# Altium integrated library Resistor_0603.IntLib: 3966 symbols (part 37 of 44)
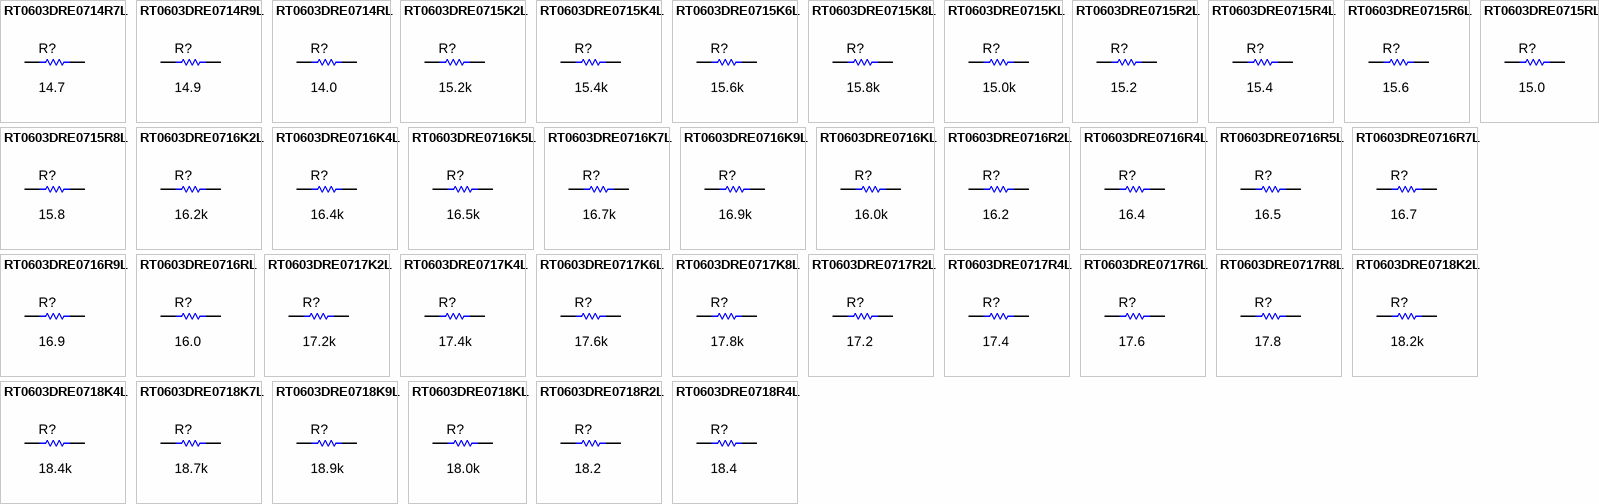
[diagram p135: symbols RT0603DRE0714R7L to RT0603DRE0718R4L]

## RT0603DRE0715R2L
designator R?  ValueDisplayed: 15.2  (hidden comment: RT0603DRE0715R2L)
RES, 15.2, 0.5%, 0.1 W, 0603; Manufacturer: Yageo America; CompType: Resistor; Value: 15.2; Value_Code: 15R2; Tolerance_%: 0.5; Power_W: 0.1; Value2: 0.1W; VDC_V: 75; TempCo: 50 ppm/C; SizeArea_mm2: 1.28; SizeX_mm: 1.6; SizeY_mm: 0.8; SizeZ_mm: 1; EIA_Code: E192; U/M: EA; AEC Category: Q200
signal-integrity model Resistor
simulation model Resistor
footprint 0603
footprint 0603M
footprint 0603L
footprint 0603_HV
footprint 0603S
pins: 1, 2

## RT0603DRE0715R4L
designator R?  ValueDisplayed: 15.4  (hidden comment: RT0603DRE0715R4L)
RES, 15.4, 0.5%, 0.1 W, 0603; Manufacturer: Yageo America; CompType: Resistor; Value: 15.4; Value_Code: 15R4; Tolerance_%: 0.5; Power_W: 0.1; Value2: 0.1W; VDC_V: 75; TempCo: 50 ppm/C; SizeArea_mm2: 1.28; SizeX_mm: 1.6; SizeY_mm: 0.8; SizeZ_mm: 1; EIA_Code: E192; U/M: EA; AEC Category: Q200
signal-integrity model Resistor
simulation model Resistor
footprint 0603
footprint 0603M
footprint 0603L
footprint 0603_HV
footprint 0603S
pins: 1, 2

## RT0603DRE0715R6L
designator R?  ValueDisplayed: 15.6  (hidden comment: RT0603DRE0715R6L)
RES, 15.6, 0.5%, 0.1 W, 0603; Manufacturer: Yageo America; CompType: Resistor; Value: 15.6; Value_Code: 15R6; Tolerance_%: 0.5; Power_W: 0.1; Value2: 0.1W; VDC_V: 75; TempCo: 50 ppm/C; SizeArea_mm2: 1.28; SizeX_mm: 1.6; SizeY_mm: 0.8; SizeZ_mm: 1; EIA_Code: E192; U/M: EA; AEC Category: Q200
signal-integrity model Resistor
simulation model Resistor
footprint 0603
footprint 0603M
footprint 0603L
footprint 0603_HV
footprint 0603S
pins: 1, 2

## RT0603DRE0715R8L
designator R?  ValueDisplayed: 15.8  (hidden comment: RT0603DRE0715R8L)
RES, 15.8, 0.5%, 0.1 W, 0603; Manufacturer: Yageo America; CompType: Resistor; Value: 15.8; Value_Code: 15R8; Tolerance_%: 0.5; Power_W: 0.1; Value2: 0.1W; VDC_V: 75; TempCo: 50 ppm/C; SizeArea_mm2: 1.28; SizeX_mm: 1.6; SizeY_mm: 0.8; SizeZ_mm: 1; EIA_Code: E192; U/M: EA; AEC Category: Q200
signal-integrity model Resistor
simulation model Resistor
footprint 0603
footprint 0603M
footprint 0603L
footprint 0603_HV
footprint 0603S
pins: 1, 2

## RT0603DRE0715RL
designator R?  ValueDisplayed: 15.0  (hidden comment: RT0603DRE0715RL)
RES, 15.0, 0.5%, 0.1 W, 0603; Manufacturer: Yageo America; CompType: Resistor; Value: 15.0; Res_ohm: 15; Value_Code: 15R0; Tolerance_%: 0.5; Power_W: 0.1; Value2: 0.1W; VDC_V: 75; TempCo: 50 ppm/C; SizeArea_mm2: 1.28; SizeX_mm: 1.6; SizeY_mm: 0.8; SizeZ_mm: 1; EIA_Code: E192; U/M: EA; AEC Category: Q200
signal-integrity model Resistor
simulation model Resistor
footprint 0603
footprint 0603M
footprint 0603L
footprint 0603_HV
footprint 0603S
pins: 1, 2

## RT0603DRE0716K2L
designator R?  ValueDisplayed: 16.2k  (hidden comment: RT0603DRE0716K2L)
RES, 16.2 k, 0.5%, 0.1 W, 0603; Manufacturer: Yageo America; CompType: Resistor; Value: 16.2k; Res_ohm: 16200; Value_Code: 16k2; Tolerance_%: 0.5; Power_W: 0.1; Value2: 0.1W; VDC_V: 75; TempCo: 50 ppm/C; SizeArea_mm2: 1.28; SizeX_mm: 1.6; SizeY_mm: 0.8; SizeZ_mm: 1; EIA_Code: E192; U/M: EA; AEC Category: Q200
signal-integrity model Resistor
simulation model Resistor
footprint 0603
footprint 0603M
footprint 0603L
footprint 0603_HV
footprint 0603S
pins: 1, 2

## RT0603DRE0716K4L
designator R?  ValueDisplayed: 16.4k  (hidden comment: RT0603DRE0716K4L)
RES, 16.4 k, 0.5%, 0.1 W, 0603; Manufacturer: Yageo America; CompType: Resistor; Value: 16.4k; Res_ohm: 16400; Value_Code: 16k4; Tolerance_%: 0.5; Power_W: 0.1; Value2: 0.1W; VDC_V: 75; TempCo: 50 ppm/C; SizeArea_mm2: 1.28; SizeX_mm: 1.6; SizeY_mm: 0.8; SizeZ_mm: 1; EIA_Code: E192; U/M: EA; AEC Category: Q200
signal-integrity model Resistor
simulation model Resistor
footprint 0603
footprint 0603M
footprint 0603L
footprint 0603_HV
footprint 0603S
pins: 1, 2

## RT0603DRE0716K5L
designator R?  ValueDisplayed: 16.5k  (hidden comment: RT0603DRE0716K5L)
RES, 16.5 k, 0.5%, 0.1 W, 0603; Manufacturer: Yageo America; CompType: Resistor; Value: 16.5k; Res_ohm: 16500; Value_Code: 16k5; Tolerance_%: 0.5; Power_W: 0.1; Value2: 0.1W; VDC_V: 75; TempCo: 50 ppm/C; SizeArea_mm2: 1.28; SizeX_mm: 1.6; SizeY_mm: 0.8; SizeZ_mm: 1; EIA_Code: E192; U/M: EA; AEC Category: Q200
signal-integrity model Resistor
simulation model Resistor
footprint 0603
footprint 0603M
footprint 0603L
footprint 0603_HV
footprint 0603S
pins: 1, 2

## RT0603DRE0716K7L
designator R?  ValueDisplayed: 16.7k  (hidden comment: RT0603DRE0716K7L)
RES, 16.7 k, 0.5%, 0.1 W, 0603; Manufacturer: Yageo America; CompType: Resistor; Value: 16.7k; Res_ohm: 16700; Value_Code: 16k7; Tolerance_%: 0.5; Power_W: 0.1; Value2: 0.1W; VDC_V: 75; TempCo: 50 ppm/C; SizeArea_mm2: 1.28; SizeX_mm: 1.6; SizeY_mm: 0.8; SizeZ_mm: 1; EIA_Code: E192; U/M: EA; AEC Category: Q200
signal-integrity model Resistor
simulation model Resistor
footprint 0603
footprint 0603M
footprint 0603L
footprint 0603_HV
footprint 0603S
pins: 1, 2

## RT0603DRE0716K9L
designator R?  ValueDisplayed: 16.9k  (hidden comment: RT0603DRE0716K9L)
RES, 16.9 k, 0.5%, 0.1 W, 0603; Manufacturer: Yageo America; CompType: Resistor; Value: 16.9k; Res_ohm: 16900; Value_Code: 16k9; Tolerance_%: 0.5; Power_W: 0.1; Value2: 0.1W; VDC_V: 75; TempCo: 50 ppm/C; SizeArea_mm2: 1.28; SizeX_mm: 1.6; SizeY_mm: 0.8; SizeZ_mm: 1; EIA_Code: E192; U/M: EA; AEC Category: Q200
signal-integrity model Resistor
simulation model Resistor
footprint 0603
footprint 0603M
footprint 0603L
footprint 0603_HV
footprint 0603S
pins: 1, 2

## RT0603DRE0716KL
designator R?  ValueDisplayed: 16.0k  (hidden comment: RT0603DRE0716KL)
RES, 16.0 k, 0.5%, 0.1 W, 0603; Manufacturer: Yageo America; CompType: Resistor; Value: 16.0k; Res_ohm: 16000; Value_Code: 16k0; Tolerance_%: 0.5; Power_W: 0.1; Value2: 0.1W; VDC_V: 75; TempCo: 50 ppm/C; SizeArea_mm2: 1.28; SizeX_mm: 1.6; SizeY_mm: 0.8; SizeZ_mm: 1; EIA_Code: E192; U/M: EA; AEC Category: Q200
signal-integrity model Resistor
simulation model Resistor
footprint 0603
footprint 0603M
footprint 0603L
footprint 0603_HV
footprint 0603S
pins: 1, 2

## RT0603DRE0716R2L
designator R?  ValueDisplayed: 16.2  (hidden comment: RT0603DRE0716R2L)
RES, 16.2, 0.5%, 0.1 W, 0603; Manufacturer: Yageo America; CompType: Resistor; Value: 16.2; Value_Code: 16R2; Tolerance_%: 0.5; Power_W: 0.1; Value2: 0.1W; VDC_V: 75; TempCo: 50 ppm/C; SizeArea_mm2: 1.28; SizeX_mm: 1.6; SizeY_mm: 0.8; SizeZ_mm: 1; EIA_Code: E192; U/M: EA; AEC Category: Q200
signal-integrity model Resistor
simulation model Resistor
footprint 0603
footprint 0603M
footprint 0603L
footprint 0603_HV
footprint 0603S
pins: 1, 2

## RT0603DRE0716R4L
designator R?  ValueDisplayed: 16.4  (hidden comment: RT0603DRE0716R4L)
RES, 16.4, 0.5%, 0.1 W, 0603; Manufacturer: Yageo America; CompType: Resistor; Value: 16.4; Value_Code: 16R4; Tolerance_%: 0.5; Power_W: 0.1; Value2: 0.1W; VDC_V: 75; TempCo: 50 ppm/C; SizeArea_mm2: 1.28; SizeX_mm: 1.6; SizeY_mm: 0.8; SizeZ_mm: 1; EIA_Code: E192; U/M: EA; AEC Category: Q200
signal-integrity model Resistor
simulation model Resistor
footprint 0603
footprint 0603M
footprint 0603L
footprint 0603_HV
footprint 0603S
pins: 1, 2

## RT0603DRE0716R5L
designator R?  ValueDisplayed: 16.5  (hidden comment: RT0603DRE0716R5L)
RES, 16.5, 0.5%, 0.1 W, 0603; Manufacturer: Yageo America; CompType: Resistor; Value: 16.5; Value_Code: 16R5; Tolerance_%: 0.5; Power_W: 0.1; Value2: 0.1W; VDC_V: 75; TempCo: 50 ppm/C; SizeArea_mm2: 1.28; SizeX_mm: 1.6; SizeY_mm: 0.8; SizeZ_mm: 1; EIA_Code: E192; U/M: EA; AEC Category: Q200
signal-integrity model Resistor
simulation model Resistor
footprint 0603
footprint 0603M
footprint 0603L
footprint 0603_HV
footprint 0603S
pins: 1, 2

## RT0603DRE0716R7L
designator R?  ValueDisplayed: 16.7  (hidden comment: RT0603DRE0716R7L)
RES, 16.7, 0.5%, 0.1 W, 0603; Manufacturer: Yageo America; CompType: Resistor; Value: 16.7; Value_Code: 16R7; Tolerance_%: 0.5; Power_W: 0.1; Value2: 0.1W; VDC_V: 75; TempCo: 50 ppm/C; SizeArea_mm2: 1.28; SizeX_mm: 1.6; SizeY_mm: 0.8; SizeZ_mm: 1; EIA_Code: E192; U/M: EA; AEC Category: Q200
signal-integrity model Resistor
simulation model Resistor
footprint 0603
footprint 0603M
footprint 0603L
footprint 0603_HV
footprint 0603S
pins: 1, 2

## RT0603DRE0716R9L
designator R?  ValueDisplayed: 16.9  (hidden comment: RT0603DRE0716R9L)
RES, 16.9, 0.5%, 0.1 W, 0603; Manufacturer: Yageo America; CompType: Resistor; Value: 16.9; Value_Code: 16R9; Tolerance_%: 0.5; Power_W: 0.1; Value2: 0.1W; VDC_V: 75; TempCo: 50 ppm/C; SizeArea_mm2: 1.28; SizeX_mm: 1.6; SizeY_mm: 0.8; SizeZ_mm: 1; EIA_Code: E192; U/M: EA; AEC Category: Q200
signal-integrity model Resistor
simulation model Resistor
footprint 0603
footprint 0603M
footprint 0603L
footprint 0603_HV
footprint 0603S
pins: 1, 2

## RT0603DRE0716RL
designator R?  ValueDisplayed: 16.0  (hidden comment: RT0603DRE0716RL)
RES, 16.0, 0.5%, 0.1 W, 0603; Manufacturer: Yageo America; CompType: Resistor; Value: 16.0; Res_ohm: 16; Value_Code: 16R0; Tolerance_%: 0.5; Power_W: 0.1; Value2: 0.1W; VDC_V: 75; TempCo: 50 ppm/C; SizeArea_mm2: 1.28; SizeX_mm: 1.6; SizeY_mm: 0.8; SizeZ_mm: 1; EIA_Code: E192; U/M: EA; AEC Category: Q200
signal-integrity model Resistor
simulation model Resistor
footprint 0603
footprint 0603M
footprint 0603L
footprint 0603_HV
footprint 0603S
pins: 1, 2

## RT0603DRE0717K2L
designator R?  ValueDisplayed: 17.2k  (hidden comment: RT0603DRE0717K2L)
RES, 17.2 k, 0.5%, 0.1 W, 0603; Manufacturer: Yageo America; CompType: Resistor; Value: 17.2k; Res_ohm: 17200; Value_Code: 17k2; Tolerance_%: 0.5; Power_W: 0.1; Value2: 0.1W; VDC_V: 75; TempCo: 50 ppm/C; SizeArea_mm2: 1.28; SizeX_mm: 1.6; SizeY_mm: 0.8; SizeZ_mm: 1; EIA_Code: E192; U/M: EA; AEC Category: Q200
signal-integrity model Resistor
simulation model Resistor
footprint 0603
footprint 0603M
footprint 0603L
footprint 0603_HV
footprint 0603S
pins: 1, 2

## RT0603DRE0717K4L
designator R?  ValueDisplayed: 17.4k  (hidden comment: RT0603DRE0717K4L)
RES, 17.4 k, 0.5%, 0.1 W, 0603; Manufacturer: Yageo America; CompType: Resistor; Value: 17.4k; Res_ohm: 17400; Value_Code: 17k4; Tolerance_%: 0.5; Power_W: 0.1; Value2: 0.1W; VDC_V: 75; TempCo: 50 ppm/C; SizeArea_mm2: 1.28; SizeX_mm: 1.6; SizeY_mm: 0.8; SizeZ_mm: 1; EIA_Code: E192; U/M: EA; AEC Category: Q200
signal-integrity model Resistor
simulation model Resistor
footprint 0603
footprint 0603M
footprint 0603L
footprint 0603_HV
footprint 0603S
pins: 1, 2

## RT0603DRE0717K6L
designator R?  ValueDisplayed: 17.6k  (hidden comment: RT0603DRE0717K6L)
RES, 17.6 k, 0.5%, 0.1 W, 0603; Manufacturer: Yageo America; CompType: Resistor; Value: 17.6k; Res_ohm: 17600; Value_Code: 17k6; Tolerance_%: 0.5; Power_W: 0.1; Value2: 0.1W; VDC_V: 75; TempCo: 50 ppm/C; SizeArea_mm2: 1.28; SizeX_mm: 1.6; SizeY_mm: 0.8; SizeZ_mm: 1; EIA_Code: E192; U/M: EA; AEC Category: Q200
signal-integrity model Resistor
simulation model Resistor
footprint 0603
footprint 0603M
footprint 0603L
footprint 0603_HV
footprint 0603S
pins: 1, 2

## RT0603DRE0717K8L
designator R?  ValueDisplayed: 17.8k  (hidden comment: RT0603DRE0717K8L)
RES, 17.8 k, 0.5%, 0.1 W, 0603; Manufacturer: Yageo America; CompType: Resistor; Value: 17.8k; Res_ohm: 17800; Value_Code: 17k8; Tolerance_%: 0.5; Power_W: 0.1; Value2: 0.1W; VDC_V: 75; TempCo: 50 ppm/C; SizeArea_mm2: 1.28; SizeX_mm: 1.6; SizeY_mm: 0.8; SizeZ_mm: 1; EIA_Code: E192; U/M: EA; AEC Category: Q200
signal-integrity model Resistor
simulation model Resistor
footprint 0603
footprint 0603M
footprint 0603L
footprint 0603_HV
footprint 0603S
pins: 1, 2

## RT0603DRE0717R2L
designator R?  ValueDisplayed: 17.2  (hidden comment: RT0603DRE0717R2L)
RES, 17.2, 0.5%, 0.1 W, 0603; Manufacturer: Yageo America; CompType: Resistor; Value: 17.2; Value_Code: 17R2; Tolerance_%: 0.5; Power_W: 0.1; Value2: 0.1W; VDC_V: 75; TempCo: 50 ppm/C; SizeArea_mm2: 1.28; SizeX_mm: 1.6; SizeY_mm: 0.8; SizeZ_mm: 1; EIA_Code: E192; U/M: EA; AEC Category: Q200
signal-integrity model Resistor
simulation model Resistor
footprint 0603
footprint 0603M
footprint 0603L
footprint 0603_HV
footprint 0603S
pins: 1, 2

## RT0603DRE0717R4L
designator R?  ValueDisplayed: 17.4  (hidden comment: RT0603DRE0717R4L)
RES, 17.4, 0.5%, 0.1 W, 0603; Manufacturer: Yageo America; CompType: Resistor; Value: 17.4; Value_Code: 17R4; Tolerance_%: 0.5; Power_W: 0.1; Value2: 0.1W; VDC_V: 75; TempCo: 50 ppm/C; SizeArea_mm2: 1.28; SizeX_mm: 1.6; SizeY_mm: 0.8; SizeZ_mm: 1; EIA_Code: E192; U/M: EA; AEC Category: Q200
signal-integrity model Resistor
simulation model Resistor
footprint 0603
footprint 0603M
footprint 0603L
footprint 0603_HV
footprint 0603S
pins: 1, 2

## RT0603DRE0717R6L
designator R?  ValueDisplayed: 17.6  (hidden comment: RT0603DRE0717R6L)
RES, 17.6, 0.5%, 0.1 W, 0603; Manufacturer: Yageo America; CompType: Resistor; Value: 17.6; Value_Code: 17R6; Tolerance_%: 0.5; Power_W: 0.1; Value2: 0.1W; VDC_V: 75; TempCo: 50 ppm/C; SizeArea_mm2: 1.28; SizeX_mm: 1.6; SizeY_mm: 0.8; SizeZ_mm: 1; EIA_Code: E192; U/M: EA; AEC Category: Q200
signal-integrity model Resistor
simulation model Resistor
footprint 0603
footprint 0603M
footprint 0603L
footprint 0603_HV
footprint 0603S
pins: 1, 2

## RT0603DRE0717R8L
designator R?  ValueDisplayed: 17.8  (hidden comment: RT0603DRE0717R8L)
RES, 17.8, 0.5%, 0.1 W, 0603; Manufacturer: Yageo America; CompType: Resistor; Value: 17.8; Value_Code: 17R8; Tolerance_%: 0.5; Power_W: 0.1; Value2: 0.1W; VDC_V: 75; TempCo: 50 ppm/C; SizeArea_mm2: 1.28; SizeX_mm: 1.6; SizeY_mm: 0.8; SizeZ_mm: 1; EIA_Code: E192; U/M: EA; AEC Category: Q200
signal-integrity model Resistor
simulation model Resistor
footprint 0603
footprint 0603M
footprint 0603L
footprint 0603_HV
footprint 0603S
pins: 1, 2

## RT0603DRE0718K2L
designator R?  ValueDisplayed: 18.2k  (hidden comment: RT0603DRE0718K2L)
RES, 18.2 k, 0.5%, 0.1 W, 0603; Manufacturer: Yageo America; CompType: Resistor; Value: 18.2k; Res_ohm: 18200; Value_Code: 18k2; Tolerance_%: 0.5; Power_W: 0.1; Value2: 0.1W; VDC_V: 75; TempCo: 50 ppm/C; SizeArea_mm2: 1.28; SizeX_mm: 1.6; SizeY_mm: 0.8; SizeZ_mm: 1; EIA_Code: E192; U/M: EA; AEC Category: Q200
signal-integrity model Resistor
simulation model Resistor
footprint 0603
footprint 0603M
footprint 0603L
footprint 0603_HV
footprint 0603S
pins: 1, 2

## RT0603DRE0718K4L
designator R?  ValueDisplayed: 18.4k  (hidden comment: RT0603DRE0718K4L)
RES, 18.4 k, 0.5%, 0.1 W, 0603; Manufacturer: Yageo America; CompType: Resistor; Value: 18.4k; Res_ohm: 18400; Value_Code: 18k4; Tolerance_%: 0.5; Power_W: 0.1; Value2: 0.1W; VDC_V: 75; TempCo: 50 ppm/C; SizeArea_mm2: 1.28; SizeX_mm: 1.6; SizeY_mm: 0.8; SizeZ_mm: 1; EIA_Code: E192; U/M: EA; AEC Category: Q200
signal-integrity model Resistor
simulation model Resistor
footprint 0603
footprint 0603M
footprint 0603L
footprint 0603_HV
footprint 0603S
pins: 1, 2

## RT0603DRE0718K7L
designator R?  ValueDisplayed: 18.7k  (hidden comment: RT0603DRE0718K7L)
RES, 18.7 k, 0.5%, 0.1 W, 0603; Manufacturer: Yageo America; CompType: Resistor; Value: 18.7k; Res_ohm: 18700; Value_Code: 18k7; Tolerance_%: 0.5; Power_W: 0.1; Value2: 0.1W; VDC_V: 75; TempCo: 50 ppm/C; SizeArea_mm2: 1.28; SizeX_mm: 1.6; SizeY_mm: 0.8; SizeZ_mm: 1; EIA_Code: E192; U/M: EA; AEC Category: Q200
signal-integrity model Resistor
simulation model Resistor
footprint 0603
footprint 0603M
footprint 0603L
footprint 0603_HV
footprint 0603S
pins: 1, 2

## RT0603DRE0718K9L
designator R?  ValueDisplayed: 18.9k  (hidden comment: RT0603DRE0718K9L)
RES, 18.9 k, 0.5%, 0.1 W, 0603; Manufacturer: Yageo America; CompType: Resistor; Value: 18.9k; Res_ohm: 18900; Value_Code: 18k9; Tolerance_%: 0.5; Power_W: 0.1; Value2: 0.1W; VDC_V: 75; TempCo: 50 ppm/C; SizeArea_mm2: 1.28; SizeX_mm: 1.6; SizeY_mm: 0.8; SizeZ_mm: 1; EIA_Code: E192; U/M: EA; AEC Category: Q200
signal-integrity model Resistor
simulation model Resistor
footprint 0603
footprint 0603M
footprint 0603L
footprint 0603_HV
footprint 0603S
pins: 1, 2

## RT0603DRE0718KL
designator R?  ValueDisplayed: 18.0k  (hidden comment: RT0603DRE0718KL)
RES, 18.0 k, 0.5%, 0.1 W, 0603; Manufacturer: Yageo America; CompType: Resistor; Value: 18.0k; Res_ohm: 18000; Value_Code: 18k0; Tolerance_%: 0.5; Power_W: 0.1; Value2: 0.1W; VDC_V: 75; TempCo: 50 ppm/C; SizeArea_mm2: 1.28; SizeX_mm: 1.6; SizeY_mm: 0.8; SizeZ_mm: 1; EIA_Code: E192; U/M: EA; AEC Category: Q200
signal-integrity model Resistor
simulation model Resistor
footprint 0603
footprint 0603M
footprint 0603L
footprint 0603_HV
footprint 0603S
pins: 1, 2

## RT0603DRE0718R2L
designator R?  ValueDisplayed: 18.2  (hidden comment: RT0603DRE0718R2L)
RES, 18.2, 0.5%, 0.1 W, 0603; Manufacturer: Yageo America; CompType: Resistor; Value: 18.2; Value_Code: 18R2; Tolerance_%: 0.5; Power_W: 0.1; Value2: 0.1W; VDC_V: 75; TempCo: 50 ppm/C; SizeArea_mm2: 1.28; SizeX_mm: 1.6; SizeY_mm: 0.8; SizeZ_mm: 1; EIA_Code: E192; U/M: EA; AEC Category: Q200
signal-integrity model Resistor
simulation model Resistor
footprint 0603
footprint 0603M
footprint 0603L
footprint 0603_HV
footprint 0603S
pins: 1, 2

## RT0603DRE0718R4L
designator R?  ValueDisplayed: 18.4  (hidden comment: RT0603DRE0718R4L)
RES, 18.4, 0.5%, 0.1 W, 0603; Manufacturer: Yageo America; CompType: Resistor; Value: 18.4; Value_Code: 18R4; Tolerance_%: 0.5; Power_W: 0.1; Value2: 0.1W; VDC_V: 75; TempCo: 50 ppm/C; SizeArea_mm2: 1.28; SizeX_mm: 1.6; SizeY_mm: 0.8; SizeZ_mm: 1; EIA_Code: E192; U/M: EA; AEC Category: Q200
signal-integrity model Resistor
simulation model Resistor
footprint 0603
footprint 0603M
footprint 0603L
footprint 0603_HV
footprint 0603S
pins: 1, 2

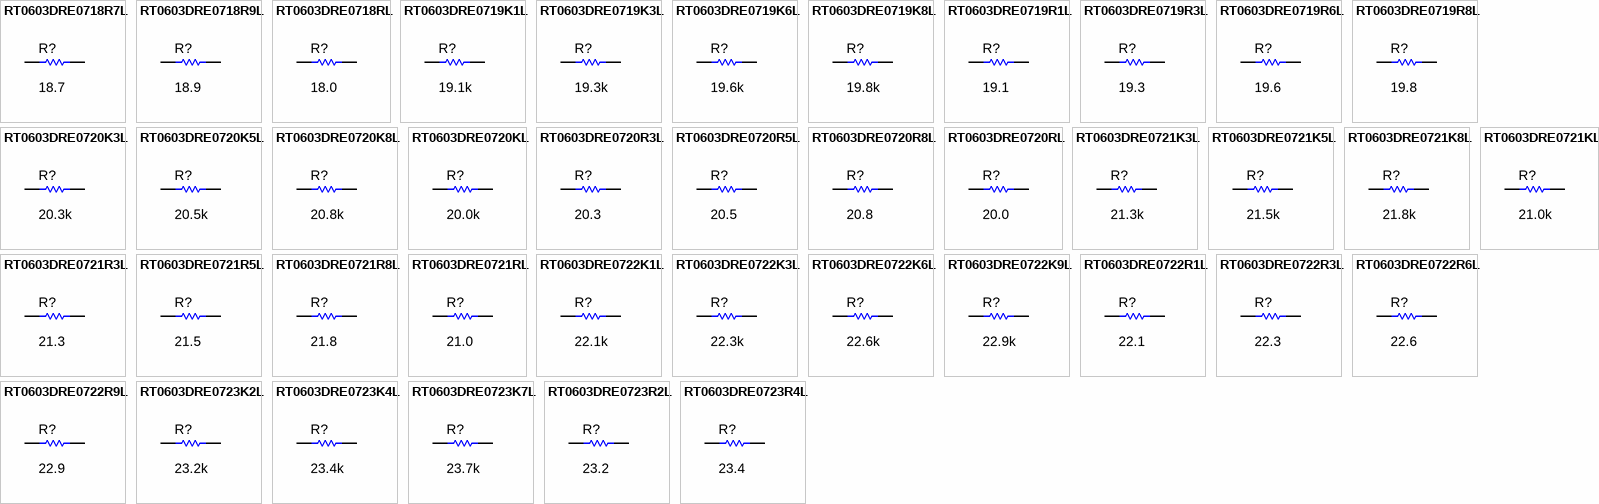
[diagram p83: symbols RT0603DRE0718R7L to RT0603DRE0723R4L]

## RT0603DRE0718R7L
designator R?  ValueDisplayed: 18.7  (hidden comment: RT0603DRE0718R7L)
RES, 18.7, 0.5%, 0.1 W, 0603; Manufacturer: Yageo America; CompType: Resistor; Value: 18.7; Value_Code: 18R7; Tolerance_%: 0.5; Power_W: 0.1; Value2: 0.1W; VDC_V: 75; TempCo: 50 ppm/C; SizeArea_mm2: 1.28; SizeX_mm: 1.6; SizeY_mm: 0.8; SizeZ_mm: 1; EIA_Code: E192; U/M: EA; AEC Category: Q200
signal-integrity model Resistor
simulation model Resistor
footprint 0603
footprint 0603M
footprint 0603L
footprint 0603_HV
footprint 0603S
pins: 1, 2

## RT0603DRE0718R9L
designator R?  ValueDisplayed: 18.9  (hidden comment: RT0603DRE0718R9L)
RES, 18.9, 0.5%, 0.1 W, 0603; Manufacturer: Yageo America; CompType: Resistor; Value: 18.9; Value_Code: 18R9; Tolerance_%: 0.5; Power_W: 0.1; Value2: 0.1W; VDC_V: 75; TempCo: 50 ppm/C; SizeArea_mm2: 1.28; SizeX_mm: 1.6; SizeY_mm: 0.8; SizeZ_mm: 1; EIA_Code: E192; U/M: EA; AEC Category: Q200
signal-integrity model Resistor
simulation model Resistor
footprint 0603
footprint 0603M
footprint 0603L
footprint 0603_HV
footprint 0603S
pins: 1, 2

## RT0603DRE0718RL
designator R?  ValueDisplayed: 18.0  (hidden comment: RT0603DRE0718RL)
RES, 18.0, 0.5%, 0.1 W, 0603; Manufacturer: Yageo America; CompType: Resistor; Value: 18.0; Res_ohm: 18; Value_Code: 18R0; Tolerance_%: 0.5; Power_W: 0.1; Value2: 0.1W; VDC_V: 75; TempCo: 50 ppm/C; SizeArea_mm2: 1.28; SizeX_mm: 1.6; SizeY_mm: 0.8; SizeZ_mm: 1; EIA_Code: E192; U/M: EA; AEC Category: Q200
signal-integrity model Resistor
simulation model Resistor
footprint 0603
footprint 0603M
footprint 0603L
footprint 0603_HV
footprint 0603S
pins: 1, 2

## RT0603DRE0719K1L
designator R?  ValueDisplayed: 19.1k  (hidden comment: RT0603DRE0719K1L)
RES, 19.1 k, 0.5%, 0.1 W, 0603; Manufacturer: Yageo America; CompType: Resistor; Value: 19.1k; Res_ohm: 19100; Value_Code: 19k1; Tolerance_%: 0.5; Power_W: 0.1; Value2: 0.1W; VDC_V: 75; TempCo: 50 ppm/C; SizeArea_mm2: 1.28; SizeX_mm: 1.6; SizeY_mm: 0.8; SizeZ_mm: 1; EIA_Code: E192; U/M: EA; AEC Category: Q200
signal-integrity model Resistor
simulation model Resistor
footprint 0603
footprint 0603M
footprint 0603L
footprint 0603_HV
footprint 0603S
pins: 1, 2

## RT0603DRE0719K3L
designator R?  ValueDisplayed: 19.3k  (hidden comment: RT0603DRE0719K3L)
RES, 19.3 k, 0.5%, 0.1 W, 0603; Manufacturer: Yageo America; CompType: Resistor; Value: 19.3k; Res_ohm: 19300; Value_Code: 19k3; Tolerance_%: 0.5; Power_W: 0.1; Value2: 0.1W; VDC_V: 75; TempCo: 50 ppm/C; SizeArea_mm2: 1.28; SizeX_mm: 1.6; SizeY_mm: 0.8; SizeZ_mm: 1; EIA_Code: E192; U/M: EA; AEC Category: Q200
signal-integrity model Resistor
simulation model Resistor
footprint 0603
footprint 0603M
footprint 0603L
footprint 0603_HV
footprint 0603S
pins: 1, 2

## RT0603DRE0719K6L
designator R?  ValueDisplayed: 19.6k  (hidden comment: RT0603DRE0719K6L)
RES, 19.6 k, 0.5%, 0.1 W, 0603; Manufacturer: Yageo America; CompType: Resistor; Value: 19.6k; Res_ohm: 19600; Value_Code: 19k6; Tolerance_%: 0.5; Power_W: 0.1; Value2: 0.1W; VDC_V: 75; TempCo: 50 ppm/C; SizeArea_mm2: 1.28; SizeX_mm: 1.6; SizeY_mm: 0.8; SizeZ_mm: 1; EIA_Code: E192; U/M: EA; AEC Category: Q200
signal-integrity model Resistor
simulation model Resistor
footprint 0603
footprint 0603M
footprint 0603L
footprint 0603_HV
footprint 0603S
pins: 1, 2

## RT0603DRE0719K8L
designator R?  ValueDisplayed: 19.8k  (hidden comment: RT0603DRE0719K8L)
RES, 19.8 k, 0.5%, 0.1 W, 0603; Manufacturer: Yageo America; CompType: Resistor; Value: 19.8k; Res_ohm: 19800; Value_Code: 19k8; Tolerance_%: 0.5; Power_W: 0.1; Value2: 0.1W; VDC_V: 75; TempCo: 50 ppm/C; SizeArea_mm2: 1.28; SizeX_mm: 1.6; SizeY_mm: 0.8; SizeZ_mm: 1; EIA_Code: E192; U/M: EA; AEC Category: Q200
signal-integrity model Resistor
simulation model Resistor
footprint 0603
footprint 0603M
footprint 0603L
footprint 0603_HV
footprint 0603S
pins: 1, 2

## RT0603DRE0719R1L
designator R?  ValueDisplayed: 19.1  (hidden comment: RT0603DRE0719R1L)
RES, 19.1, 0.5%, 0.1 W, 0603; Manufacturer: Yageo America; CompType: Resistor; Value: 19.1; Value_Code: 19R1; Tolerance_%: 0.5; Power_W: 0.1; Value2: 0.1W; VDC_V: 75; TempCo: 50 ppm/C; SizeArea_mm2: 1.28; SizeX_mm: 1.6; SizeY_mm: 0.8; SizeZ_mm: 1; EIA_Code: E192; U/M: EA; AEC Category: Q200
signal-integrity model Resistor
simulation model Resistor
footprint 0603
footprint 0603M
footprint 0603L
footprint 0603_HV
footprint 0603S
pins: 1, 2

## RT0603DRE0719R3L
designator R?  ValueDisplayed: 19.3  (hidden comment: RT0603DRE0719R3L)
RES, 19.3, 0.5%, 0.1 W, 0603; Manufacturer: Yageo America; CompType: Resistor; Value: 19.3; Value_Code: 19R3; Tolerance_%: 0.5; Power_W: 0.1; Value2: 0.1W; VDC_V: 75; TempCo: 50 ppm/C; SizeArea_mm2: 1.28; SizeX_mm: 1.6; SizeY_mm: 0.8; SizeZ_mm: 1; EIA_Code: E192; U/M: EA; AEC Category: Q200
signal-integrity model Resistor
simulation model Resistor
footprint 0603
footprint 0603M
footprint 0603L
footprint 0603_HV
footprint 0603S
pins: 1, 2

## RT0603DRE0719R6L
designator R?  ValueDisplayed: 19.6  (hidden comment: RT0603DRE0719R6L)
RES, 19.6, 0.5%, 0.1 W, 0603; Manufacturer: Yageo America; CompType: Resistor; Value: 19.6; Value_Code: 19R6; Tolerance_%: 0.5; Power_W: 0.1; Value2: 0.1W; VDC_V: 75; TempCo: 50 ppm/C; SizeArea_mm2: 1.28; SizeX_mm: 1.6; SizeY_mm: 0.8; SizeZ_mm: 1; EIA_Code: E192; U/M: EA; AEC Category: Q200
signal-integrity model Resistor
simulation model Resistor
footprint 0603
footprint 0603M
footprint 0603L
footprint 0603_HV
footprint 0603S
pins: 1, 2

## RT0603DRE0719R8L
designator R?  ValueDisplayed: 19.8  (hidden comment: RT0603DRE0719R8L)
RES, 19.8, 0.5%, 0.1 W, 0603; Manufacturer: Yageo America; CompType: Resistor; Value: 19.8; Value_Code: 19R8; Tolerance_%: 0.5; Power_W: 0.1; Value2: 0.1W; VDC_V: 75; TempCo: 50 ppm/C; SizeArea_mm2: 1.28; SizeX_mm: 1.6; SizeY_mm: 0.8; SizeZ_mm: 1; EIA_Code: E192; U/M: EA; AEC Category: Q200
signal-integrity model Resistor
simulation model Resistor
footprint 0603
footprint 0603M
footprint 0603L
footprint 0603_HV
footprint 0603S
pins: 1, 2

## RT0603DRE0720K3L
designator R?  ValueDisplayed: 20.3k  (hidden comment: RT0603DRE0720K3L)
RES, 20.3 k, 0.5%, 0.1 W, 0603; Manufacturer: Yageo America; CompType: Resistor; Value: 20.3k; Res_ohm: 20300; Value_Code: 20k3; Tolerance_%: 0.5; Power_W: 0.1; Value2: 0.1W; VDC_V: 75; TempCo: 50 ppm/C; SizeArea_mm2: 1.28; SizeX_mm: 1.6; SizeY_mm: 0.8; SizeZ_mm: 1; EIA_Code: E192; U/M: EA; AEC Category: Q200
signal-integrity model Resistor
simulation model Resistor
footprint 0603
footprint 0603M
footprint 0603L
footprint 0603_HV
footprint 0603S
pins: 1, 2

## RT0603DRE0720K5L
designator R?  ValueDisplayed: 20.5k  (hidden comment: RT0603DRE0720K5L)
RES, 20.5 k, 0.5%, 0.1 W, 0603; Manufacturer: Yageo America; CompType: Resistor; Value: 20.5k; Res_ohm: 20500; Value_Code: 20k5; Tolerance_%: 0.5; Power_W: 0.1; Value2: 0.1W; VDC_V: 75; TempCo: 50 ppm/C; SizeArea_mm2: 1.28; SizeX_mm: 1.6; SizeY_mm: 0.8; SizeZ_mm: 1; EIA_Code: E192; U/M: EA; AEC Category: Q200
signal-integrity model Resistor
simulation model Resistor
footprint 0603
footprint 0603M
footprint 0603L
footprint 0603_HV
footprint 0603S
pins: 1, 2

## RT0603DRE0720K8L
designator R?  ValueDisplayed: 20.8k  (hidden comment: RT0603DRE0720K8L)
RES, 20.8 k, 0.5%, 0.1 W, 0603; Manufacturer: Yageo America; CompType: Resistor; Value: 20.8k; Res_ohm: 20800; Value_Code: 20k8; Tolerance_%: 0.5; Power_W: 0.1; Value2: 0.1W; VDC_V: 75; TempCo: 50 ppm/C; SizeArea_mm2: 1.28; SizeX_mm: 1.6; SizeY_mm: 0.8; SizeZ_mm: 1; EIA_Code: E192; U/M: EA; AEC Category: Q200
signal-integrity model Resistor
simulation model Resistor
footprint 0603
footprint 0603M
footprint 0603L
footprint 0603_HV
footprint 0603S
pins: 1, 2

## RT0603DRE0720KL
designator R?  ValueDisplayed: 20.0k  (hidden comment: RT0603DRE0720KL)
RES, 20.0 k, 0.5%, 0.1 W, 0603; Manufacturer: Yageo America; CompType: Resistor; Value: 20.0k; Res_ohm: 20000; Value_Code: 20k0; Tolerance_%: 0.5; Power_W: 0.1; Value2: 0.1W; VDC_V: 75; TempCo: 50 ppm/C; SizeArea_mm2: 1.28; SizeX_mm: 1.6; SizeY_mm: 0.8; SizeZ_mm: 1; EIA_Code: E192; U/M: EA; AEC Category: Q200
signal-integrity model Resistor
simulation model Resistor
footprint 0603
footprint 0603M
footprint 0603L
footprint 0603_HV
footprint 0603S
pins: 1, 2

## RT0603DRE0720R3L
designator R?  ValueDisplayed: 20.3  (hidden comment: RT0603DRE0720R3L)
RES, 20.3, 0.5%, 0.1 W, 0603; Manufacturer: Yageo America; CompType: Resistor; Value: 20.3; Value_Code: 20R3; Tolerance_%: 0.5; Power_W: 0.1; Value2: 0.1W; VDC_V: 75; TempCo: 50 ppm/C; SizeArea_mm2: 1.28; SizeX_mm: 1.6; SizeY_mm: 0.8; SizeZ_mm: 1; EIA_Code: E192; U/M: EA; AEC Category: Q200
signal-integrity model Resistor
simulation model Resistor
footprint 0603
footprint 0603M
footprint 0603L
footprint 0603_HV
footprint 0603S
pins: 1, 2

## RT0603DRE0720R5L
designator R?  ValueDisplayed: 20.5  (hidden comment: RT0603DRE0720R5L)
RES, 20.5, 0.5%, 0.1 W, 0603; Manufacturer: Yageo America; CompType: Resistor; Value: 20.5; Value_Code: 20R5; Tolerance_%: 0.5; Power_W: 0.1; Value2: 0.1W; VDC_V: 75; TempCo: 50 ppm/C; SizeArea_mm2: 1.28; SizeX_mm: 1.6; SizeY_mm: 0.8; SizeZ_mm: 1; EIA_Code: E192; U/M: EA; AEC Category: Q200
signal-integrity model Resistor
simulation model Resistor
footprint 0603
footprint 0603M
footprint 0603L
footprint 0603_HV
footprint 0603S
pins: 1, 2

## RT0603DRE0720R8L
designator R?  ValueDisplayed: 20.8  (hidden comment: RT0603DRE0720R8L)
RES, 20.8, 0.5%, 0.1 W, 0603; Manufacturer: Yageo America; CompType: Resistor; Value: 20.8; Value_Code: 20R8; Tolerance_%: 0.5; Power_W: 0.1; Value2: 0.1W; VDC_V: 75; TempCo: 50 ppm/C; SizeArea_mm2: 1.28; SizeX_mm: 1.6; SizeY_mm: 0.8; SizeZ_mm: 1; EIA_Code: E192; U/M: EA; AEC Category: Q200
signal-integrity model Resistor
simulation model Resistor
footprint 0603
footprint 0603M
footprint 0603L
footprint 0603_HV
footprint 0603S
pins: 1, 2

## RT0603DRE0720RL
designator R?  ValueDisplayed: 20.0  (hidden comment: RT0603DRE0720RL)
RES, 20.0, 0.5%, 0.1 W, 0603; Manufacturer: Yageo America; CompType: Resistor; Value: 20.0; Res_ohm: 20; Value_Code: 20R0; Tolerance_%: 0.5; Power_W: 0.1; Value2: 0.1W; VDC_V: 75; TempCo: 50 ppm/C; SizeArea_mm2: 1.28; SizeX_mm: 1.6; SizeY_mm: 0.8; SizeZ_mm: 1; EIA_Code: E192; U/M: EA; AEC Category: Q200
signal-integrity model Resistor
simulation model Resistor
footprint 0603
footprint 0603M
footprint 0603L
footprint 0603_HV
footprint 0603S
pins: 1, 2

## RT0603DRE0721K3L
designator R?  ValueDisplayed: 21.3k  (hidden comment: RT0603DRE0721K3L)
RES, 21.3 k, 0.5%, 0.1 W, 0603; Manufacturer: Yageo America; CompType: Resistor; Value: 21.3k; Res_ohm: 21300; Value_Code: 21k3; Tolerance_%: 0.5; Power_W: 0.1; Value2: 0.1W; VDC_V: 75; TempCo: 50 ppm/C; SizeArea_mm2: 1.28; SizeX_mm: 1.6; SizeY_mm: 0.8; SizeZ_mm: 1; EIA_Code: E192; U/M: EA; AEC Category: Q200
signal-integrity model Resistor
simulation model Resistor
footprint 0603
footprint 0603M
footprint 0603L
footprint 0603_HV
footprint 0603S
pins: 1, 2

## RT0603DRE0721K5L
designator R?  ValueDisplayed: 21.5k  (hidden comment: RT0603DRE0721K5L)
RES, 21.5 k, 0.5%, 0.1 W, 0603; Manufacturer: Yageo America; CompType: Resistor; Value: 21.5k; Res_ohm: 21500; Value_Code: 21k5; Tolerance_%: 0.5; Power_W: 0.1; Value2: 0.1W; VDC_V: 75; TempCo: 50 ppm/C; SizeArea_mm2: 1.28; SizeX_mm: 1.6; SizeY_mm: 0.8; SizeZ_mm: 1; EIA_Code: E192; U/M: EA; AEC Category: Q200
signal-integrity model Resistor
simulation model Resistor
footprint 0603
footprint 0603M
footprint 0603L
footprint 0603_HV
footprint 0603S
pins: 1, 2

## RT0603DRE0721K8L
designator R?  ValueDisplayed: 21.8k  (hidden comment: RT0603DRE0721K8L)
RES, 21.8 k, 0.5%, 0.1 W, 0603; Manufacturer: Yageo America; CompType: Resistor; Value: 21.8k; Res_ohm: 21800; Value_Code: 21k8; Tolerance_%: 0.5; Power_W: 0.1; Value2: 0.1W; VDC_V: 75; TempCo: 50 ppm/C; SizeArea_mm2: 1.28; SizeX_mm: 1.6; SizeY_mm: 0.8; SizeZ_mm: 1; EIA_Code: E192; U/M: EA; AEC Category: Q200
signal-integrity model Resistor
simulation model Resistor
footprint 0603
footprint 0603M
footprint 0603L
footprint 0603_HV
footprint 0603S
pins: 1, 2

## RT0603DRE0721KL
designator R?  ValueDisplayed: 21.0k  (hidden comment: RT0603DRE0721KL)
RES, 21.0 k, 0.5%, 0.1 W, 0603; Manufacturer: Yageo America; CompType: Resistor; Value: 21.0k; Res_ohm: 21000; Value_Code: 21k0; Tolerance_%: 0.5; Power_W: 0.1; Value2: 0.1W; VDC_V: 75; TempCo: 50 ppm/C; SizeArea_mm2: 1.28; SizeX_mm: 1.6; SizeY_mm: 0.8; SizeZ_mm: 1; EIA_Code: E192; U/M: EA; AEC Category: Q200
signal-integrity model Resistor
simulation model Resistor
footprint 0603
footprint 0603M
footprint 0603L
footprint 0603_HV
footprint 0603S
pins: 1, 2

## RT0603DRE0721R3L
designator R?  ValueDisplayed: 21.3  (hidden comment: RT0603DRE0721R3L)
RES, 21.3, 0.5%, 0.1 W, 0603; Manufacturer: Yageo America; CompType: Resistor; Value: 21.3; Value_Code: 21R3; Tolerance_%: 0.5; Power_W: 0.1; Value2: 0.1W; VDC_V: 75; TempCo: 50 ppm/C; SizeArea_mm2: 1.28; SizeX_mm: 1.6; SizeY_mm: 0.8; SizeZ_mm: 1; EIA_Code: E192; U/M: EA; AEC Category: Q200
signal-integrity model Resistor
simulation model Resistor
footprint 0603
footprint 0603M
footprint 0603L
footprint 0603_HV
footprint 0603S
pins: 1, 2

## RT0603DRE0721R5L
designator R?  ValueDisplayed: 21.5  (hidden comment: RT0603DRE0721R5L)
RES, 21.5, 0.5%, 0.1 W, 0603; Manufacturer: Yageo America; CompType: Resistor; Value: 21.5; Value_Code: 21R5; Tolerance_%: 0.5; Power_W: 0.1; Value2: 0.1W; VDC_V: 75; TempCo: 50 ppm/C; SizeArea_mm2: 1.28; SizeX_mm: 1.6; SizeY_mm: 0.8; SizeZ_mm: 1; EIA_Code: E192; U/M: EA; AEC Category: Q200
signal-integrity model Resistor
simulation model Resistor
footprint 0603
footprint 0603M
footprint 0603L
footprint 0603_HV
footprint 0603S
pins: 1, 2

## RT0603DRE0721R8L
designator R?  ValueDisplayed: 21.8  (hidden comment: RT0603DRE0721R8L)
RES, 21.8, 0.5%, 0.1 W, 0603; Manufacturer: Yageo America; CompType: Resistor; Value: 21.8; Value_Code: 21R8; Tolerance_%: 0.5; Power_W: 0.1; Value2: 0.1W; VDC_V: 75; TempCo: 50 ppm/C; SizeArea_mm2: 1.28; SizeX_mm: 1.6; SizeY_mm: 0.8; SizeZ_mm: 1; EIA_Code: E192; U/M: EA; AEC Category: Q200
signal-integrity model Resistor
simulation model Resistor
footprint 0603
footprint 0603M
footprint 0603L
footprint 0603_HV
footprint 0603S
pins: 1, 2

## RT0603DRE0721RL
designator R?  ValueDisplayed: 21.0  (hidden comment: RT0603DRE0721RL)
RES, 21.0, 0.5%, 0.1 W, 0603; Manufacturer: Yageo America; CompType: Resistor; Value: 21.0; Res_ohm: 21; Value_Code: 21R0; Tolerance_%: 0.5; Power_W: 0.1; Value2: 0.1W; VDC_V: 75; TempCo: 50 ppm/C; SizeArea_mm2: 1.28; SizeX_mm: 1.6; SizeY_mm: 0.8; SizeZ_mm: 1; EIA_Code: E192; U/M: EA; AEC Category: Q200
signal-integrity model Resistor
simulation model Resistor
footprint 0603
footprint 0603M
footprint 0603L
footprint 0603_HV
footprint 0603S
pins: 1, 2

## RT0603DRE0722K1L
designator R?  ValueDisplayed: 22.1k  (hidden comment: RT0603DRE0722K1L)
RES, 22.1 k, 0.5%, 0.1 W, 0603; Manufacturer: Yageo America; CompType: Resistor; Value: 22.1k; Res_ohm: 22100; Value_Code: 22k1; Tolerance_%: 0.5; Power_W: 0.1; Value2: 0.1W; VDC_V: 75; TempCo: 50 ppm/C; SizeArea_mm2: 1.28; SizeX_mm: 1.6; SizeY_mm: 0.8; SizeZ_mm: 1; EIA_Code: E192; U/M: EA; AEC Category: Q200
signal-integrity model Resistor
simulation model Resistor
footprint 0603
footprint 0603M
footprint 0603L
footprint 0603_HV
footprint 0603S
pins: 1, 2

## RT0603DRE0722K3L
designator R?  ValueDisplayed: 22.3k  (hidden comment: RT0603DRE0722K3L)
RES, 22.3 k, 0.5%, 0.1 W, 0603; Manufacturer: Yageo America; CompType: Resistor; Value: 22.3k; Res_ohm: 22300; Value_Code: 22k3; Tolerance_%: 0.5; Power_W: 0.1; Value2: 0.1W; VDC_V: 75; TempCo: 50 ppm/C; SizeArea_mm2: 1.28; SizeX_mm: 1.6; SizeY_mm: 0.8; SizeZ_mm: 1; EIA_Code: E192; U/M: EA; AEC Category: Q200
signal-integrity model Resistor
simulation model Resistor
footprint 0603
footprint 0603M
footprint 0603L
footprint 0603_HV
footprint 0603S
pins: 1, 2

## RT0603DRE0722K6L
designator R?  ValueDisplayed: 22.6k  (hidden comment: RT0603DRE0722K6L)
RES, 22.6 k, 0.5%, 0.1 W, 0603; Manufacturer: Yageo America; CompType: Resistor; Value: 22.6k; Res_ohm: 22600; Value_Code: 22k6; Tolerance_%: 0.5; Power_W: 0.1; Value2: 0.1W; VDC_V: 75; TempCo: 50 ppm/C; SizeArea_mm2: 1.28; SizeX_mm: 1.6; SizeY_mm: 0.8; SizeZ_mm: 1; EIA_Code: E192; U/M: EA; AEC Category: Q200
signal-integrity model Resistor
simulation model Resistor
footprint 0603
footprint 0603M
footprint 0603L
footprint 0603_HV
footprint 0603S
pins: 1, 2

## RT0603DRE0722K9L
designator R?  ValueDisplayed: 22.9k  (hidden comment: RT0603DRE0722K9L)
RES, 22.9 k, 0.5%, 0.1 W, 0603; Manufacturer: Yageo America; CompType: Resistor; Value: 22.9k; Res_ohm: 22900; Value_Code: 22k9; Tolerance_%: 0.5; Power_W: 0.1; Value2: 0.1W; VDC_V: 75; TempCo: 50 ppm/C; SizeArea_mm2: 1.28; SizeX_mm: 1.6; SizeY_mm: 0.8; SizeZ_mm: 1; EIA_Code: E192; U/M: EA; AEC Category: Q200
signal-integrity model Resistor
simulation model Resistor
footprint 0603
footprint 0603M
footprint 0603L
footprint 0603_HV
footprint 0603S
pins: 1, 2

## RT0603DRE0722R1L
designator R?  ValueDisplayed: 22.1  (hidden comment: RT0603DRE0722R1L)
RES, 22.1, 0.5%, 0.1 W, 0603; Manufacturer: Yageo America; CompType: Resistor; Value: 22.1; Value_Code: 22R1; Tolerance_%: 0.5; Power_W: 0.1; Value2: 0.1W; VDC_V: 75; TempCo: 50 ppm/C; SizeArea_mm2: 1.28; SizeX_mm: 1.6; SizeY_mm: 0.8; SizeZ_mm: 1; EIA_Code: E192; U/M: EA; AEC Category: Q200
signal-integrity model Resistor
simulation model Resistor
footprint 0603
footprint 0603M
footprint 0603L
footprint 0603_HV
footprint 0603S
pins: 1, 2

## RT0603DRE0722R3L
designator R?  ValueDisplayed: 22.3  (hidden comment: RT0603DRE0722R3L)
RES, 22.3, 0.5%, 0.1 W, 0603; Manufacturer: Yageo America; CompType: Resistor; Value: 22.3; Value_Code: 22R3; Tolerance_%: 0.5; Power_W: 0.1; Value2: 0.1W; VDC_V: 75; TempCo: 50 ppm/C; SizeArea_mm2: 1.28; SizeX_mm: 1.6; SizeY_mm: 0.8; SizeZ_mm: 1; EIA_Code: E192; U/M: EA; AEC Category: Q200
signal-integrity model Resistor
simulation model Resistor
footprint 0603
footprint 0603M
footprint 0603L
footprint 0603_HV
footprint 0603S
pins: 1, 2

## RT0603DRE0722R6L
designator R?  ValueDisplayed: 22.6  (hidden comment: RT0603DRE0722R6L)
RES, 22.6, 0.5%, 0.1 W, 0603; Manufacturer: Yageo America; CompType: Resistor; Value: 22.6; Value_Code: 22R6; Tolerance_%: 0.5; Power_W: 0.1; Value2: 0.1W; VDC_V: 75; TempCo: 50 ppm/C; SizeArea_mm2: 1.28; SizeX_mm: 1.6; SizeY_mm: 0.8; SizeZ_mm: 1; EIA_Code: E192; U/M: EA; AEC Category: Q200
signal-integrity model Resistor
simulation model Resistor
footprint 0603
footprint 0603M
footprint 0603L
footprint 0603_HV
footprint 0603S
pins: 1, 2

## RT0603DRE0722R9L
designator R?  ValueDisplayed: 22.9  (hidden comment: RT0603DRE0722R9L)
RES, 22.9, 0.5%, 0.1 W, 0603; Manufacturer: Yageo America; CompType: Resistor; Value: 22.9; Value_Code: 22R9; Tolerance_%: 0.5; Power_W: 0.1; Value2: 0.1W; VDC_V: 75; TempCo: 50 ppm/C; SizeArea_mm2: 1.28; SizeX_mm: 1.6; SizeY_mm: 0.8; SizeZ_mm: 1; EIA_Code: E192; U/M: EA; AEC Category: Q200
signal-integrity model Resistor
simulation model Resistor
footprint 0603
footprint 0603M
footprint 0603L
footprint 0603_HV
footprint 0603S
pins: 1, 2

## RT0603DRE0723K2L
designator R?  ValueDisplayed: 23.2k  (hidden comment: RT0603DRE0723K2L)
RES, 23.2 k, 0.5%, 0.1 W, 0603; Manufacturer: Yageo America; CompType: Resistor; Value: 23.2k; Res_ohm: 23200; Value_Code: 23k2; Tolerance_%: 0.5; Power_W: 0.1; Value2: 0.1W; VDC_V: 75; TempCo: 50 ppm/C; SizeArea_mm2: 1.28; SizeX_mm: 1.6; SizeY_mm: 0.8; SizeZ_mm: 1; EIA_Code: E192; U/M: EA; AEC Category: Q200
signal-integrity model Resistor
simulation model Resistor
footprint 0603
footprint 0603M
footprint 0603L
footprint 0603_HV
footprint 0603S
pins: 1, 2

## RT0603DRE0723K4L
designator R?  ValueDisplayed: 23.4k  (hidden comment: RT0603DRE0723K4L)
RES, 23.4 k, 0.5%, 0.1 W, 0603; Manufacturer: Yageo America; CompType: Resistor; Value: 23.4k; Res_ohm: 23400; Value_Code: 23k4; Tolerance_%: 0.5; Power_W: 0.1; Value2: 0.1W; VDC_V: 75; TempCo: 50 ppm/C; SizeArea_mm2: 1.28; SizeX_mm: 1.6; SizeY_mm: 0.8; SizeZ_mm: 1; EIA_Code: E192; U/M: EA; AEC Category: Q200
signal-integrity model Resistor
simulation model Resistor
footprint 0603
footprint 0603M
footprint 0603L
footprint 0603_HV
footprint 0603S
pins: 1, 2

## RT0603DRE0723K7L
designator R?  ValueDisplayed: 23.7k  (hidden comment: RT0603DRE0723K7L)
RES, 23.7 k, 0.5%, 0.1 W, 0603; Manufacturer: Yageo America; CompType: Resistor; Value: 23.7k; Res_ohm: 23700; Value_Code: 23k7; Tolerance_%: 0.5; Power_W: 0.1; Value2: 0.1W; VDC_V: 75; TempCo: 50 ppm/C; SizeArea_mm2: 1.28; SizeX_mm: 1.6; SizeY_mm: 0.8; SizeZ_mm: 1; EIA_Code: E192; U/M: EA; AEC Category: Q200
signal-integrity model Resistor
simulation model Resistor
footprint 0603
footprint 0603M
footprint 0603L
footprint 0603_HV
footprint 0603S
pins: 1, 2

## RT0603DRE0723R2L
designator R?  ValueDisplayed: 23.2  (hidden comment: RT0603DRE0723R2L)
RES, 23.2, 0.5%, 0.1 W, 0603; Manufacturer: Yageo America; CompType: Resistor; Value: 23.2; Value_Code: 23R2; Tolerance_%: 0.5; Power_W: 0.1; Value2: 0.1W; VDC_V: 75; TempCo: 50 ppm/C; SizeArea_mm2: 1.28; SizeX_mm: 1.6; SizeY_mm: 0.8; SizeZ_mm: 1; EIA_Code: E192; U/M: EA; AEC Category: Q200
signal-integrity model Resistor
simulation model Resistor
footprint 0603
footprint 0603M
footprint 0603L
footprint 0603_HV
footprint 0603S
pins: 1, 2

## RT0603DRE0723R4L
designator R?  ValueDisplayed: 23.4  (hidden comment: RT0603DRE0723R4L)
RES, 23.4, 0.5%, 0.1 W, 0603; Manufacturer: Yageo America; CompType: Resistor; Value: 23.4; Value_Code: 23R4; Tolerance_%: 0.5; Power_W: 0.1; Value2: 0.1W; VDC_V: 75; TempCo: 50 ppm/C; SizeArea_mm2: 1.28; SizeX_mm: 1.6; SizeY_mm: 0.8; SizeZ_mm: 1; EIA_Code: E192; U/M: EA; AEC Category: Q200
signal-integrity model Resistor
simulation model Resistor
footprint 0603
footprint 0603M
footprint 0603L
footprint 0603_HV
footprint 0603S
pins: 1, 2

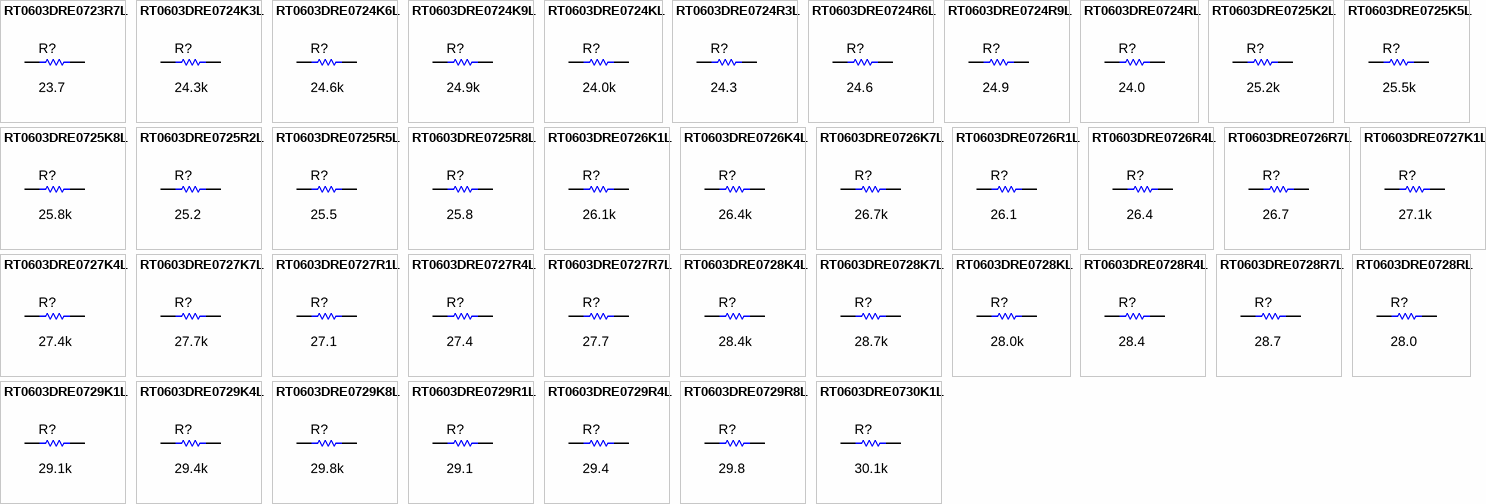
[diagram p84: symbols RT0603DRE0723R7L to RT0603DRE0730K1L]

## RT0603DRE0723R7L
designator R?  ValueDisplayed: 23.7  (hidden comment: RT0603DRE0723R7L)
RES, 23.7, 0.5%, 0.1 W, 0603; Manufacturer: Yageo America; CompType: Resistor; Value: 23.7; Value_Code: 23R7; Tolerance_%: 0.5; Power_W: 0.1; Value2: 0.1W; VDC_V: 75; TempCo: 50 ppm/C; SizeArea_mm2: 1.28; SizeX_mm: 1.6; SizeY_mm: 0.8; SizeZ_mm: 1; EIA_Code: E192; U/M: EA; AEC Category: Q200
signal-integrity model Resistor
simulation model Resistor
footprint 0603
footprint 0603M
footprint 0603L
footprint 0603_HV
footprint 0603S
pins: 1, 2

## RT0603DRE0724K3L
designator R?  ValueDisplayed: 24.3k  (hidden comment: RT0603DRE0724K3L)
RES, 24.3 k, 0.5%, 0.1 W, 0603; Manufacturer: Yageo America; CompType: Resistor; Value: 24.3k; Res_ohm: 24300; Value_Code: 24k3; Tolerance_%: 0.5; Power_W: 0.1; Value2: 0.1W; VDC_V: 75; TempCo: 50 ppm/C; SizeArea_mm2: 1.28; SizeX_mm: 1.6; SizeY_mm: 0.8; SizeZ_mm: 1; EIA_Code: E192; U/M: EA; AEC Category: Q200
signal-integrity model Resistor
simulation model Resistor
footprint 0603
footprint 0603M
footprint 0603L
footprint 0603_HV
footprint 0603S
pins: 1, 2

## RT0603DRE0724K6L
designator R?  ValueDisplayed: 24.6k  (hidden comment: RT0603DRE0724K6L)
RES, 24.6 k, 0.5%, 0.1 W, 0603; Manufacturer: Yageo America; CompType: Resistor; Value: 24.6k; Res_ohm: 24600; Value_Code: 24k6; Tolerance_%: 0.5; Power_W: 0.1; Value2: 0.1W; VDC_V: 75; TempCo: 50 ppm/C; SizeArea_mm2: 1.28; SizeX_mm: 1.6; SizeY_mm: 0.8; SizeZ_mm: 1; EIA_Code: E192; U/M: EA; AEC Category: Q200
signal-integrity model Resistor
simulation model Resistor
footprint 0603
footprint 0603M
footprint 0603L
footprint 0603_HV
footprint 0603S
pins: 1, 2

## RT0603DRE0724K9L
designator R?  ValueDisplayed: 24.9k  (hidden comment: RT0603DRE0724K9L)
RES, 24.9 k, 0.5%, 0.1 W, 0603; Manufacturer: Yageo America; CompType: Resistor; Value: 24.9k; Res_ohm: 24900; Value_Code: 24k9; Tolerance_%: 0.5; Power_W: 0.1; Value2: 0.1W; VDC_V: 75; TempCo: 50 ppm/C; SizeArea_mm2: 1.28; SizeX_mm: 1.6; SizeY_mm: 0.8; SizeZ_mm: 1; EIA_Code: E192; U/M: EA; AEC Category: Q200
signal-integrity model Resistor
simulation model Resistor
footprint 0603
footprint 0603M
footprint 0603L
footprint 0603_HV
footprint 0603S
pins: 1, 2

## RT0603DRE0724KL
designator R?  ValueDisplayed: 24.0k  (hidden comment: RT0603DRE0724KL)
RES, 24.0 k, 0.5%, 0.1 W, 0603; Manufacturer: Yageo America; CompType: Resistor; Value: 24.0k; Res_ohm: 24000; Value_Code: 24k0; Tolerance_%: 0.5; Power_W: 0.1; Value2: 0.1W; VDC_V: 75; TempCo: 50 ppm/C; SizeArea_mm2: 1.28; SizeX_mm: 1.6; SizeY_mm: 0.8; SizeZ_mm: 1; EIA_Code: E192; U/M: EA; AEC Category: Q200
signal-integrity model Resistor
simulation model Resistor
footprint 0603
footprint 0603M
footprint 0603L
footprint 0603_HV
footprint 0603S
pins: 1, 2

## RT0603DRE0724R3L
designator R?  ValueDisplayed: 24.3  (hidden comment: RT0603DRE0724R3L)
RES, 24.3, 0.5%, 0.1 W, 0603; Manufacturer: Yageo America; CompType: Resistor; Value: 24.3; Value_Code: 24R3; Tolerance_%: 0.5; Power_W: 0.1; Value2: 0.1W; VDC_V: 75; TempCo: 50 ppm/C; SizeArea_mm2: 1.28; SizeX_mm: 1.6; SizeY_mm: 0.8; SizeZ_mm: 1; EIA_Code: E192; U/M: EA; AEC Category: Q200
signal-integrity model Resistor
simulation model Resistor
footprint 0603
footprint 0603M
footprint 0603L
footprint 0603_HV
footprint 0603S
pins: 1, 2

## RT0603DRE0724R6L
designator R?  ValueDisplayed: 24.6  (hidden comment: RT0603DRE0724R6L)
RES, 24.6, 0.5%, 0.1 W, 0603; Manufacturer: Yageo America; CompType: Resistor; Value: 24.6; Value_Code: 24R6; Tolerance_%: 0.5; Power_W: 0.1; Value2: 0.1W; VDC_V: 75; TempCo: 50 ppm/C; SizeArea_mm2: 1.28; SizeX_mm: 1.6; SizeY_mm: 0.8; SizeZ_mm: 1; EIA_Code: E192; U/M: EA; AEC Category: Q200
signal-integrity model Resistor
simulation model Resistor
footprint 0603
footprint 0603M
footprint 0603L
footprint 0603_HV
footprint 0603S
pins: 1, 2

## RT0603DRE0724R9L
designator R?  ValueDisplayed: 24.9  (hidden comment: RT0603DRE0724R9L)
RES, 24.9, 0.5%, 0.1 W, 0603; Manufacturer: Yageo America; CompType: Resistor; Value: 24.9; Value_Code: 24R9; Tolerance_%: 0.5; Power_W: 0.1; Value2: 0.1W; VDC_V: 75; TempCo: 50 ppm/C; SizeArea_mm2: 1.28; SizeX_mm: 1.6; SizeY_mm: 0.8; SizeZ_mm: 1; EIA_Code: E192; U/M: EA; AEC Category: Q200
signal-integrity model Resistor
simulation model Resistor
footprint 0603
footprint 0603M
footprint 0603L
footprint 0603_HV
footprint 0603S
pins: 1, 2

## RT0603DRE0724RL
designator R?  ValueDisplayed: 24.0  (hidden comment: RT0603DRE0724RL)
RES, 24.0, 0.5%, 0.1 W, 0603; Manufacturer: Yageo America; CompType: Resistor; Value: 24.0; Res_ohm: 24; Value_Code: 24R0; Tolerance_%: 0.5; Power_W: 0.1; Value2: 0.1W; VDC_V: 75; TempCo: 50 ppm/C; SizeArea_mm2: 1.28; SizeX_mm: 1.6; SizeY_mm: 0.8; SizeZ_mm: 1; EIA_Code: E192; U/M: EA; AEC Category: Q200
signal-integrity model Resistor
simulation model Resistor
footprint 0603
footprint 0603M
footprint 0603L
footprint 0603_HV
footprint 0603S
pins: 1, 2

## RT0603DRE0725K2L
designator R?  ValueDisplayed: 25.2k  (hidden comment: RT0603DRE0725K2L)
RES, 25.2 k, 0.5%, 0.1 W, 0603; Manufacturer: Yageo America; CompType: Resistor; Value: 25.2k; Res_ohm: 25200; Value_Code: 25k2; Tolerance_%: 0.5; Power_W: 0.1; Value2: 0.1W; VDC_V: 75; TempCo: 50 ppm/C; SizeArea_mm2: 1.28; SizeX_mm: 1.6; SizeY_mm: 0.8; SizeZ_mm: 1; EIA_Code: E192; U/M: EA; AEC Category: Q200
signal-integrity model Resistor
simulation model Resistor
footprint 0603
footprint 0603M
footprint 0603L
footprint 0603_HV
footprint 0603S
pins: 1, 2

## RT0603DRE0725K5L
designator R?  ValueDisplayed: 25.5k  (hidden comment: RT0603DRE0725K5L)
RES, 25.5 k, 0.5%, 0.1 W, 0603; Manufacturer: Yageo America; CompType: Resistor; Value: 25.5k; Res_ohm: 25500; Value_Code: 25k5; Tolerance_%: 0.5; Power_W: 0.1; Value2: 0.1W; VDC_V: 75; TempCo: 50 ppm/C; SizeArea_mm2: 1.28; SizeX_mm: 1.6; SizeY_mm: 0.8; SizeZ_mm: 1; EIA_Code: E192; U/M: EA; AEC Category: Q200
signal-integrity model Resistor
simulation model Resistor
footprint 0603
footprint 0603M
footprint 0603L
footprint 0603_HV
footprint 0603S
pins: 1, 2

## RT0603DRE0725K8L
designator R?  ValueDisplayed: 25.8k  (hidden comment: RT0603DRE0725K8L)
RES, 25.8 k, 0.5%, 0.1 W, 0603; Manufacturer: Yageo America; CompType: Resistor; Value: 25.8k; Res_ohm: 25800; Value_Code: 25k8; Tolerance_%: 0.5; Power_W: 0.1; Value2: 0.1W; VDC_V: 75; TempCo: 50 ppm/C; SizeArea_mm2: 1.28; SizeX_mm: 1.6; SizeY_mm: 0.8; SizeZ_mm: 1; EIA_Code: E192; U/M: EA; AEC Category: Q200
signal-integrity model Resistor
simulation model Resistor
footprint 0603
footprint 0603M
footprint 0603L
footprint 0603_HV
footprint 0603S
pins: 1, 2

## RT0603DRE0725R2L
designator R?  ValueDisplayed: 25.2  (hidden comment: RT0603DRE0725R2L)
RES, 25.2, 0.5%, 0.1 W, 0603; Manufacturer: Yageo America; CompType: Resistor; Value: 25.2; Value_Code: 25R2; Tolerance_%: 0.5; Power_W: 0.1; Value2: 0.1W; VDC_V: 75; TempCo: 50 ppm/C; SizeArea_mm2: 1.28; SizeX_mm: 1.6; SizeY_mm: 0.8; SizeZ_mm: 1; EIA_Code: E192; U/M: EA; AEC Category: Q200
signal-integrity model Resistor
simulation model Resistor
footprint 0603
footprint 0603M
footprint 0603L
footprint 0603_HV
footprint 0603S
pins: 1, 2

## RT0603DRE0725R5L
designator R?  ValueDisplayed: 25.5  (hidden comment: RT0603DRE0725R5L)
RES, 25.5, 0.5%, 0.1 W, 0603; Manufacturer: Yageo America; CompType: Resistor; Value: 25.5; Value_Code: 25R5; Tolerance_%: 0.5; Power_W: 0.1; Value2: 0.1W; VDC_V: 75; TempCo: 50 ppm/C; SizeArea_mm2: 1.28; SizeX_mm: 1.6; SizeY_mm: 0.8; SizeZ_mm: 1; EIA_Code: E192; U/M: EA; AEC Category: Q200
signal-integrity model Resistor
simulation model Resistor
footprint 0603
footprint 0603M
footprint 0603L
footprint 0603_HV
footprint 0603S
pins: 1, 2

## RT0603DRE0725R8L
designator R?  ValueDisplayed: 25.8  (hidden comment: RT0603DRE0725R8L)
RES, 25.8, 0.5%, 0.1 W, 0603; Manufacturer: Yageo America; CompType: Resistor; Value: 25.8; Value_Code: 25R8; Tolerance_%: 0.5; Power_W: 0.1; Value2: 0.1W; VDC_V: 75; TempCo: 50 ppm/C; SizeArea_mm2: 1.28; SizeX_mm: 1.6; SizeY_mm: 0.8; SizeZ_mm: 1; EIA_Code: E192; U/M: EA; AEC Category: Q200
signal-integrity model Resistor
simulation model Resistor
footprint 0603
footprint 0603M
footprint 0603L
footprint 0603_HV
footprint 0603S
pins: 1, 2

## RT0603DRE0726K1L
designator R?  ValueDisplayed: 26.1k  (hidden comment: RT0603DRE0726K1L)
RES, 26.1 k, 0.5%, 0.1 W, 0603; Manufacturer: Yageo America; CompType: Resistor; Value: 26.1k; Res_ohm: 26100; Value_Code: 26k1; Tolerance_%: 0.5; Power_W: 0.1; Value2: 0.1W; VDC_V: 75; TempCo: 50 ppm/C; SizeArea_mm2: 1.28; SizeX_mm: 1.6; SizeY_mm: 0.8; SizeZ_mm: 1; EIA_Code: E192; U/M: EA; AEC Category: Q200
signal-integrity model Resistor
simulation model Resistor
footprint 0603
footprint 0603M
footprint 0603L
footprint 0603_HV
footprint 0603S
pins: 1, 2

## RT0603DRE0726K4L
designator R?  ValueDisplayed: 26.4k  (hidden comment: RT0603DRE0726K4L)
RES, 26.4 k, 0.5%, 0.1 W, 0603; Manufacturer: Yageo America; CompType: Resistor; Value: 26.4k; Res_ohm: 26400; Value_Code: 26k4; Tolerance_%: 0.5; Power_W: 0.1; Value2: 0.1W; VDC_V: 75; TempCo: 50 ppm/C; SizeArea_mm2: 1.28; SizeX_mm: 1.6; SizeY_mm: 0.8; SizeZ_mm: 1; EIA_Code: E192; U/M: EA; AEC Category: Q200
signal-integrity model Resistor
simulation model Resistor
footprint 0603
footprint 0603M
footprint 0603L
footprint 0603_HV
footprint 0603S
pins: 1, 2

## RT0603DRE0726K7L
designator R?  ValueDisplayed: 26.7k  (hidden comment: RT0603DRE0726K7L)
RES, 26.7 k, 0.5%, 0.1 W, 0603; Manufacturer: Yageo America; CompType: Resistor; Value: 26.7k; Res_ohm: 26700; Value_Code: 26k7; Tolerance_%: 0.5; Power_W: 0.1; Value2: 0.1W; VDC_V: 75; TempCo: 50 ppm/C; SizeArea_mm2: 1.28; SizeX_mm: 1.6; SizeY_mm: 0.8; SizeZ_mm: 1; EIA_Code: E192; U/M: EA; AEC Category: Q200
signal-integrity model Resistor
simulation model Resistor
footprint 0603
footprint 0603M
footprint 0603L
footprint 0603_HV
footprint 0603S
pins: 1, 2

## RT0603DRE0726R1L
designator R?  ValueDisplayed: 26.1  (hidden comment: RT0603DRE0726R1L)
RES, 26.1, 0.5%, 0.1 W, 0603; Manufacturer: Yageo America; CompType: Resistor; Value: 26.1; Value_Code: 26R1; Tolerance_%: 0.5; Power_W: 0.1; Value2: 0.1W; VDC_V: 75; TempCo: 50 ppm/C; SizeArea_mm2: 1.28; SizeX_mm: 1.6; SizeY_mm: 0.8; SizeZ_mm: 1; EIA_Code: E192; U/M: EA; AEC Category: Q200
signal-integrity model Resistor
simulation model Resistor
footprint 0603
footprint 0603M
footprint 0603L
footprint 0603_HV
footprint 0603S
pins: 1, 2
